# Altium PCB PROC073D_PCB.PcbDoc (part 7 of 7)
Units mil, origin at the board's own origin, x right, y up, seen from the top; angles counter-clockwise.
Board outline 2165.35 x 2695.12 mil, 8 copper layers (Top Layer, L2_GND, L3_SIGNAL 1, L4_SIGNAL 2, L5_SIGNAL 3, L6_SIGNAL 4, L7_GND, Bottom Layer), stack 56.1 mil thick; 414 components, 319 nets, 1353 pads, 1669 vias.
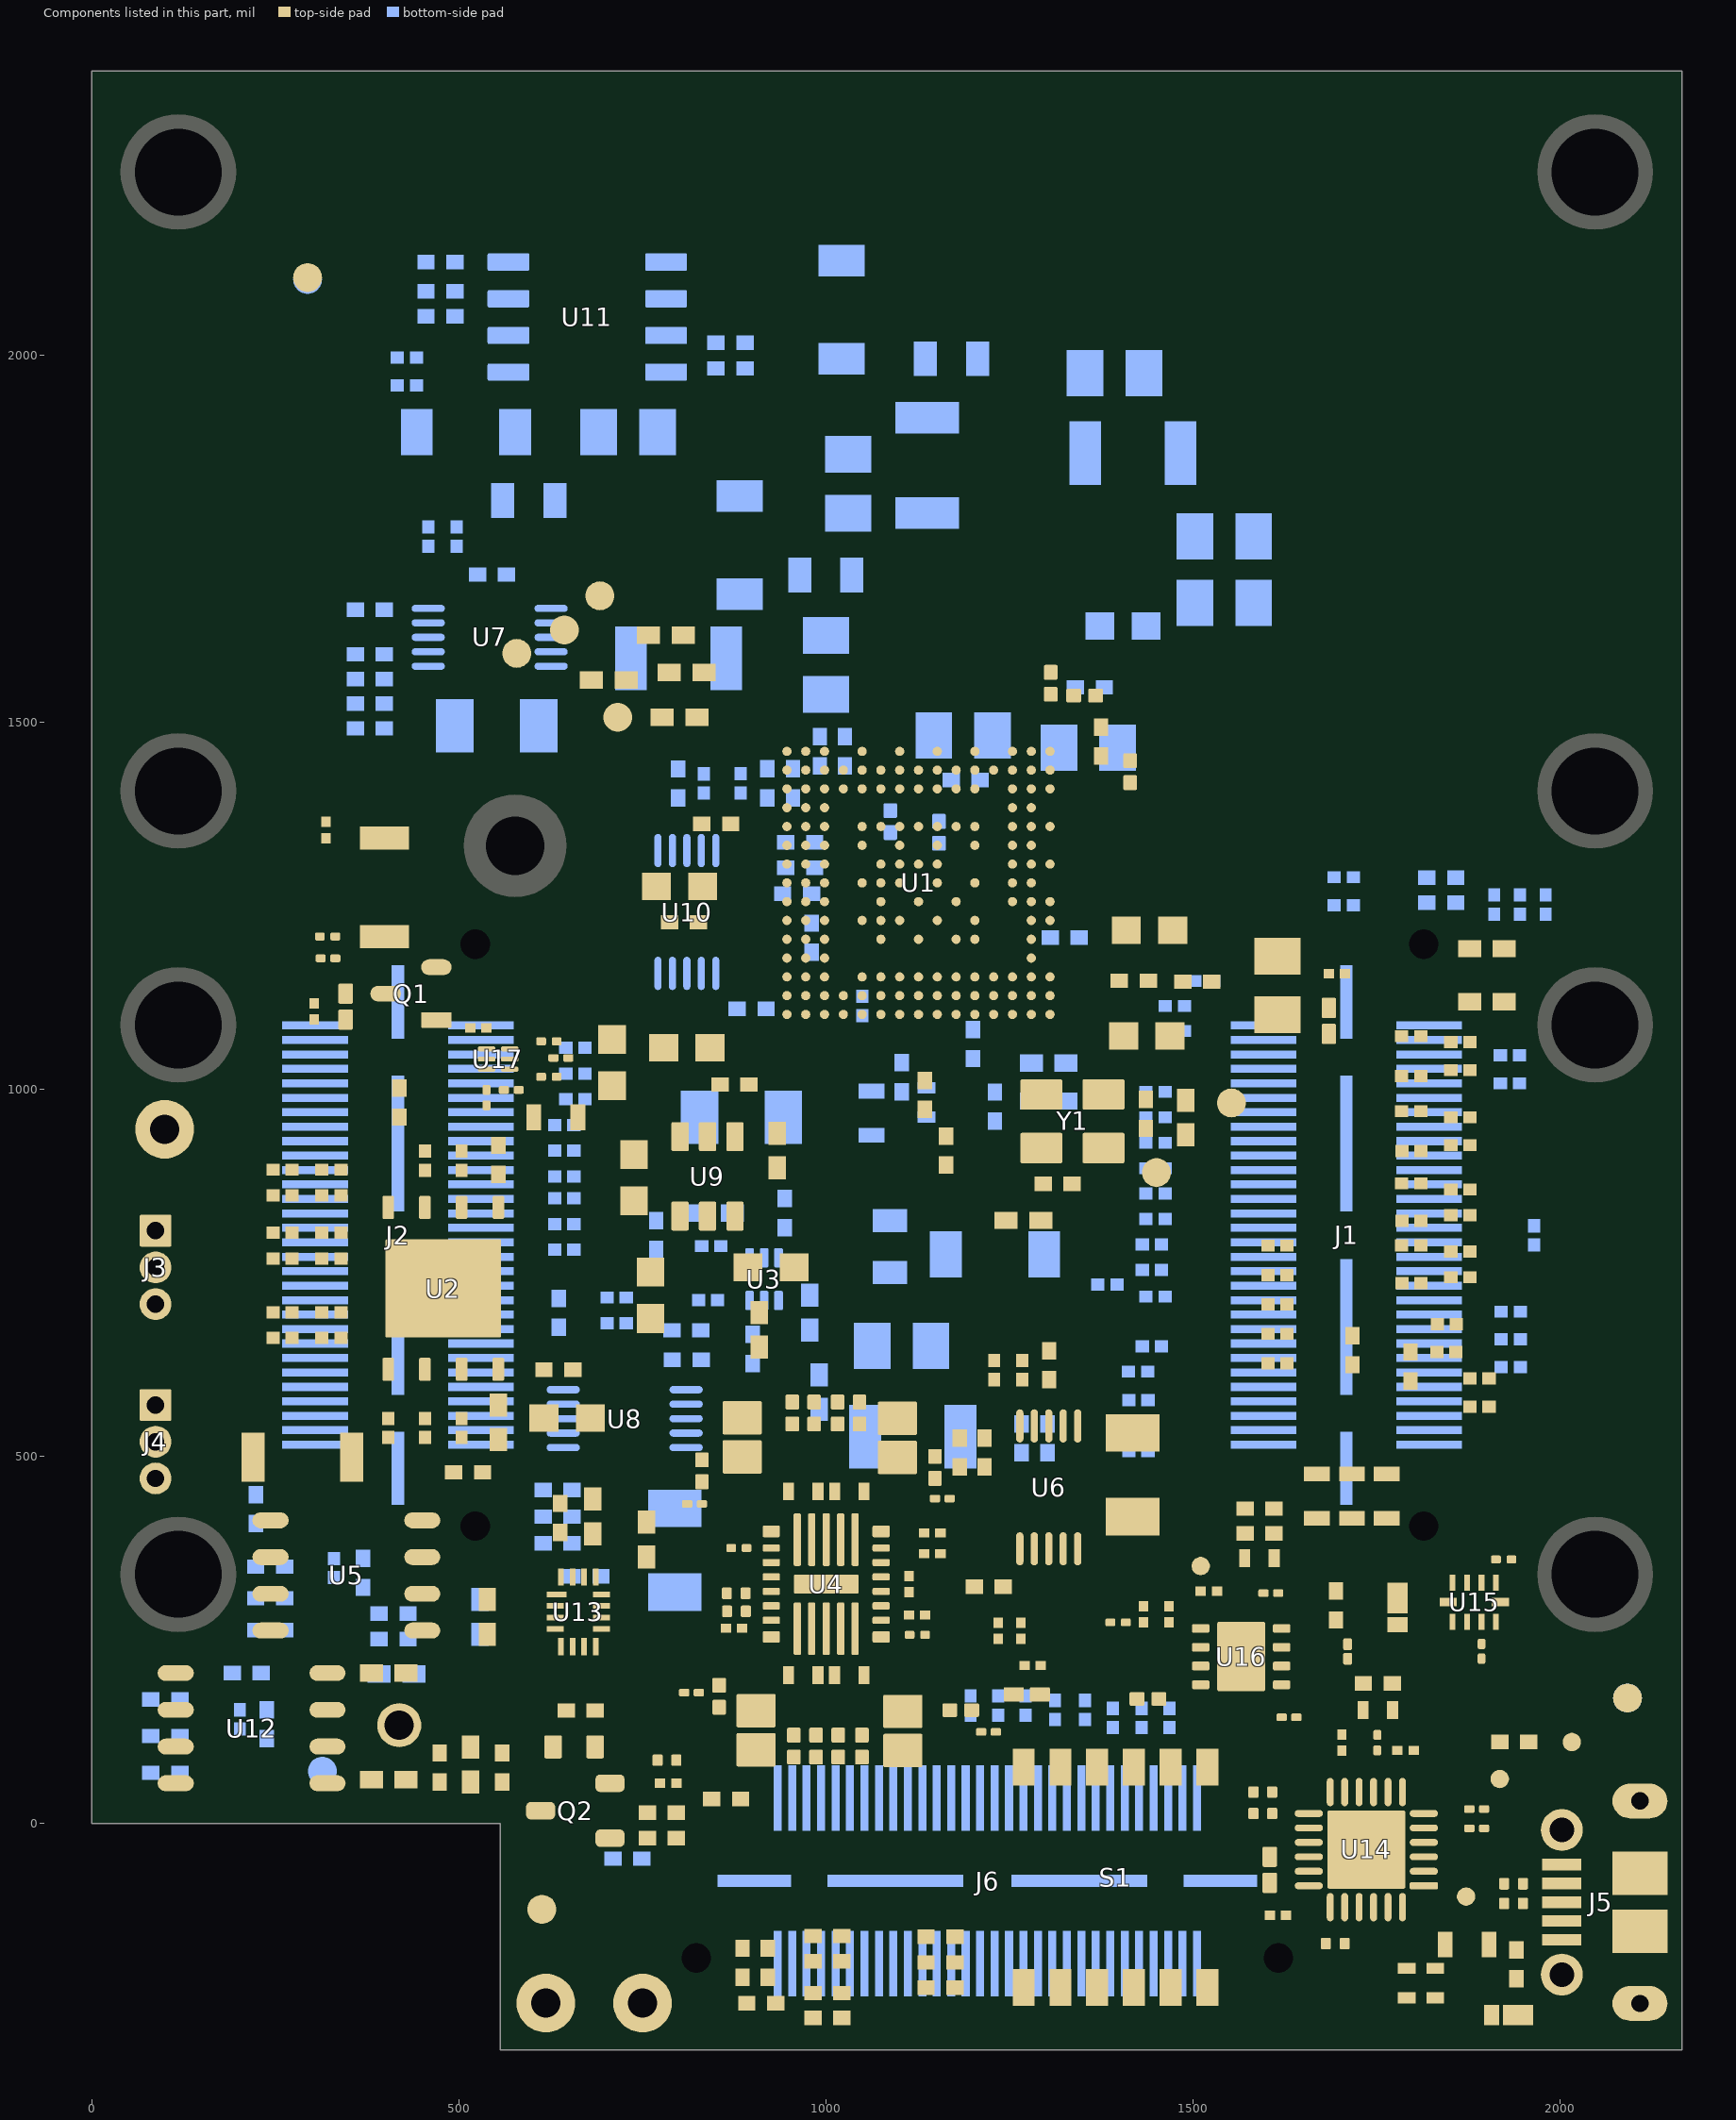
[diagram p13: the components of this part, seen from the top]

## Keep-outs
L2_GND:
  circle w1: c1074.8,1434.59 r7.87
  circle w1: c1177.16,1434.59 r7.87
  circle w1: c1125.98,1434.59 r7.87
  circle w1: c1279.53,1281.05 r7.87
  circle w1: c1279.52,1383.41 r7.87
  circle w1: c1279.52,1332.23 r7.87
  circle w1: c522.48,1197.95 r32
  circle w1: c1023.62,1434.59 r7.87
L3_SIGNAL 1:
  circle w1: c522.48,1197.95 r32
L5_SIGNAL 3:
  circle w1: c522.48,1197.95 r30
L7_GND:
  circle w1: c522.48,1196.95 r32
Bottom Layer:
  circle w1: c522.48,1197.95 r27.7
Keep-Out Layer:
  circle w1: c823.48,-182.98 r32
  circle w1: c1616,-182.98 r32
  circle w1: c522.48,1197.43 r32
  circle w1: c1813.86,1197.69 r32
  circle w1: c1813.86,405.17 r31
  circle w1: c522.48,404.91 r32
  lines w10: -5,-5 551.54,-5 551.54,-313.34 2170.35,-313.34 2170.35,2391.78 -5,2391.78 -5,-5
  text ".Layer_Name" at -423,-1637.06 h60

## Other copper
Top Layer:
  pour cut-out: 1039.36,1434.59 cw(c1023.62,1434.59) 1023.62,1418.85 cw(c1023.62,1434.59) 1007.88,1434.59 cw(c1023.62,1434.59) 1023.62,1450.33 cw(c1023.62,1434.59)
  pour cut-out: 1090.54,1434.59 cw(c1074.8,1434.59) 1074.8,1418.85 cw(c1074.8,1434.59) 1059.06,1434.59 cw(c1074.8,1434.59) 1074.8,1450.33 cw(c1074.8,1434.59)
  pour cut-out: 1141.72,1434.59 cw(c1125.98,1434.59) 1125.98,1418.85 cw(c1125.98,1434.59) 1110.24,1434.59 cw(c1125.98,1434.59) 1125.98,1450.33 cw(c1125.98,1434.59)
  pour cut-out: 1192.9,1434.59 cw(c1177.16,1434.59) 1177.16,1418.85 cw(c1177.16,1434.59) 1161.42,1434.59 cw(c1177.16,1434.59) 1177.16,1450.33 cw(c1177.16,1434.59)
  pour cut-out: 1295.26,1383.41 cw(c1279.52,1383.41) 1279.52,1367.67 cw(c1279.52,1383.41) 1263.78,1383.41 cw(c1279.52,1383.41) 1279.52,1399.15 cw(c1279.52,1383.41)
  pour cut-out: 1295.26,1332.23 cw(c1279.52,1332.23) 1279.52,1316.49 cw(c1279.52,1332.23) 1263.78,1332.23 cw(c1279.52,1332.23) 1279.52,1347.97 cw(c1279.52,1332.23)
  pour cut-out: 1295.26,1281.05 cw(c1279.52,1281.05) 1279.52,1265.31 cw(c1279.52,1281.05) 1263.78,1281.05 cw(c1279.52,1281.05) 1279.52,1296.79 cw(c1279.52,1281.05)
  pour cut-out: 556.52,-284.49 2140,-284.49 2140,2365.43 30,2365.43 29.99,0 0,0 0,2386.79 2165.35,2386.78 2165.36,-308.35 556.51,-308.34
  pour cut-out: 578.43,31.17 556.54,31.17 556.54,-284.48 578.43,-284.48
  pour cut-out: 578.43,31.17 29.99,31.17 29.99,0 578.43,0
  region net GND: 815.55,442.32 818.07,440.03 818.07,430.09 815.12,427.14 813.42,428.84 813.42,440.2
  region net GND: 816.41,441.54
  region net SW2_CAP: 824.15,446.21 824.15,427.99 826.75,425.39 828.9,427.54 828.9,443.25 825.66,446.48
  region net SW2_CAP: 823.19,446.32
  region net NetD1_2: 1921.76,-277.2 1926.51,-281.95 1926.51,-237.67 1921.76,-237.67
  region net 5V_IN_USB: 1913.29,-241.4 1916.65,-244.76 1916.65,-274.59 1913.28,-277.96 1909.04,-273.72 1909.04,-243.99 1910.77,-242.26
  region net 5V_IN_USB: 1913.62,-243.99
  region net NetD2_2: 1756.18,286.5 1795.39,286.5 1799.66,290.77 1757.72,290.77 1756.34,289.39
  region net 5V_IN: 1762.6,281.23 1802.62,281.23 1797.57,276.18 1762.22,276.18 1759.89,278.51
  region net GND: 1701.54,224.73 1701.54,228.44 1705.56,232.47 1723.33,232.47 1728.39,237.53 1728.39,230.46 1720.9,222.97 1703.31,222.97
  region net 5V_IN_SW: 1722.23,242.78 1717.81,242.78 1700.69,242.78 1695.5,237.59 1696.69,236.4 1715.85,236.4
  text ".Layer_Name" at -423,-1637.06 h60
L2_GND:
  pour cut-out: 1031.49,1434.59 cw(c1023.62,1434.59) 1023.62,1426.72 cw(c1023.62,1434.59) 1015.75,1434.59 cw(c1023.62,1434.59) 1023.62,1442.46 cw(c1023.62,1434.59)
  pour cut-out: 1031.49,1434.59 cw(c1023.62,1434.59) 1023.62,1426.72 cw(c1023.62,1434.59) 1015.75,1434.59 cw(c1023.62,1434.59) 1023.62,1442.46 cw(c1023.62,1434.59)
  pour cut-out: 1250,1044.43 1236,1030.43 1236,901.43 1257,880.43 1257,842.43 1263,836.43 1320,836.43 1344,860.43 1403,860.42 1411,868.43 1411,893.43 1433,915.43 1462,915.43 1470,923.43 1470,1000.43 1435,1035.43 1373,1035.43 1373,1054.43 1454.66,1054.43 1486.15,1022.93 1486.15,918.72 1465.09,897.66 1444.23,897.66 1426,879.43 1426,871.43 1397,842.43 1354.51,842.43 1329.44,817.37 1257.06,817.37 1236.03,838.4 1236.02,879.21 1216.02,899.23 1216.02,1040.43 1230.01,1054.42 1249.76,1054.43
  pour cut-out: 1236.78,1061.19 1245.87,1070.29 1245.87,1082.56 1075.37,1253.06 1075.37,1275.22 1033,1317.59 1033,1366.85 1014.95,1384.9 977.13,1422.72 977.13,1494.94 809.63,1662.44 809.63,2366.28 788,2366.28 788,1651.83 956.28,1483.55 956.28,1410.48 1012.83,1353.93 1012.83,1304.31 1057.82,1259.32 1057.82,1240.15
  pour cut-out: 2140.93,1585.87 1997.92,1585.87 1885.11,1473.06 1885.11,1444.65 1682.7,1242.24 1621.63,1242.24 1392.37,1242.24 1354.68,1204.55 1354.68,1127.22 1354.68,1040.8 1374.9,1040.8 1374.9,1151.62 1374.9,1194.05 1400.28,1219.43 1691.88,1219.43 1908.35,1435.9 1908.35,1460.99 2011.45,1564.09 2140.93,1564.09
  pour cut-out: 578.43,31.17 556.54,31.17 556.54,-284.48 578.43,-284.48
  pour cut-out: 556.52,-284.49 2140,-284.49 2140,2365.43 30,2365.43 29.99,0 0,0 0,2386.79 2165.35,2386.78 2165.36,-308.35 556.51,-308.34
  pour cut-out: 578.43,31.17 29.99,31.17 29.99,0 578.43,0
  pour cut-out: 1218.81,895.32 1218.81,879.53 1213.48,874.2 1221.37,866.31 1227.89,866.31 1227.89,871.64 1236.96,880.72 1224.73,892.95 1224.73,894.73
  pour cut-out: 1029,1382.43 1044,1382.43 1044,1367.19 1041.24,1364.43 1023,1364.43 1023,1376.43
  pour cut-out: 1060,1198.59 1075,1198.59 1075,1183.36 1072.23,1180.59 1054,1180.59 1054,1192.59
  pour cut-out: 1085.74,1196.59 1100.74,1196.59 1100.74,1181.36 1097.97,1178.59 1079.74,1178.59 1079.74,1190.59
  pour cut-out: 1255,1216.59 1270,1216.59 1270,1201.36 1267.23,1198.59 1249,1198.59 1249,1210.59
  pour cut-out: 1023.84,1257.18 1023.84,1272.18 1039.07,1272.18 1041.84,1269.41 1041.84,1251.18 1029.84,1251.18
  pour cut-out: 1031,1322.59 1046,1322.59 1046,1307.36 1043.23,1304.59 1025,1304.59 1025,1316.59
  pour cut-out: 885,1252.78 900,1252.78 900,1237.54 897.23,1234.78 879,1234.78 879,1246.78
  pour cut-out: 1158.84,1369.43 1158.84,1384.43 1174.07,1384.43 1176.84,1381.66 1176.84,1363.43 1164.84,1363.43
  pour cut-out: 1225.74,1184.36 1240.95,1190.79 1243.46,1180.6 1244.87,1176.68 1229.98,1169 1225.59,1183.89
  pour cut-out: 1223.69,1185.58 1242.47,1192.83 1246.63,1175.99 1229.52,1167.18 1223.69,1184.8
  text ".Layer_Name" at -423,-1637.06 h60
L3_SIGNAL 1:
  pour cut-out: 556.52,-284.49 2140,-284.49 2140,2365.43 30,2365.43 29.99,0 0,0 0,2386.79 2165.35,2386.78 2165.36,-308.35 556.51,-308.34
  pour cut-out: 578.43,31.17 29.99,31.17 29.99,0 578.43,0
  pour cut-out: 578.43,31.17 556.54,31.17 556.54,-284.48 578.43,-284.48
  pour cut-out: 1180.53,1386.9 1183,1384.43 1178.14,1379.57 1178.14,1366.29 1173.94,1362.1 1154.33,1362.1 1146.87,1369.56 1146.87,1375.5 1158.27,1386.9
  text ".Layer_Name" at -423,-1637.06 h60
L5_SIGNAL 3:
  pour cut-out: 578.43,31.17 556.54,31.17 556.54,-284.48 578.43,-284.48
  pour cut-out: 556.52,-284.49 2140,-284.49 2140,2365.43 30,2365.43 29.99,0 0,0 0,2386.79 2165.35,2386.78 2165.36,-308.35 556.51,-308.34
  pour cut-out: 578.43,31.17 29.99,31.17 29.99,0 578.43,0
  region net RADAR_QSPI_CS: 600.56,552.15
  pour cut-out: 1006.6,1594.42
  text ".Layer_Name" at -423,-1637.06 h60
L7_GND:
  pour cut-out: 578.43,31.17 556.54,31.17 556.54,-284.48 578.43,-284.48
  pour cut-out: 556.52,-284.49 2140,-284.49 2140,2365.43 30,2365.43 29.99,0 0,0 0,2386.79 2165.35,2386.78 2165.36,-308.35 556.51,-308.34
  pour cut-out: 578.43,31.17 29.99,31.17 29.99,0 578.43,0
  pour cut-out: 885.48,860.02 885.48,862.59 891.89,869 897.35,869 906.33,860.02 898.95,852.64 898.95,849.76 895.1,849.76 886.44,858.42
  pour cut-out: 1743.38,629.67 1743.38,632.24 1749.79,638.65 1755.25,638.65 1764.23,629.67 1756.85,622.29 1756.85,619.41 1753,619.41 1744.34,628.07
  pour cut-out: 1048,1202.49 1021.98,1202.49 1021.99,1220.02 1048,1220.02
  pour cut-out: 1048.65,1253.69 1022.63,1253.69 1022.64,1271.22 1048.65,1271.22
  pour cut-out: 1022.8,1324.95 1048.81,1324.95 1048.81,1307.41 1022.8,1307.41
  pour cut-out: 1180.98,1365.43 1154.96,1365.43 1154.96,1382.97 1180.98,1382.97
  pour cut-out: 1064,1200.43 1080,1184.43 1080,1180.43 1071,1171.43 1068,1171.43 1052,1187.43 1052,1194.43 1059,1201.43 1062,1201.43
  text ".Layer_Name" at -423,-1637.06 h60
L4_SIGNAL 2:
  pour cut-out: 578.43,31.17 556.54,31.17 556.54,-284.48 578.43,-284.48
  pour cut-out: 556.52,-284.49 2140,-284.49 2140,2365.43 30,2365.43 29.99,0 0,0 0,2386.79 2165.35,2386.78 2165.36,-308.35 556.51,-308.34
  pour cut-out: 578.43,31.17 29.99,31.17 29.99,0 578.43,0
  pour cut-out: 95.09,462.76 34.43,402.11 34.43,248.32 63.31,219.43 132.08,219.43 208.64,295.99 208.64,457.4 203.28,462.76
  pour cut-out: 606.77,-203.05 595.32,-203.05 574.72,-223.66 574.72,-271.99 598.01,-295.28 640.51,-295.28 664.11,-271.68 664.11,-228.06 640.51,-204.46
  text ".Layer_Name" at -423,-1637.06 h60
L6_SIGNAL 4:
  pour cut-out: 578.43,31.17 556.54,31.17 556.54,-284.48 578.43,-284.48
  pour cut-out: 556.52,-284.49 2140,-284.49 2140,2365.43 30,2365.43 29.99,0 0,0 0,2386.79 2165.35,2386.78 2165.36,-308.35 556.51,-308.34
  pour cut-out: 578.43,31.17 29.99,31.17 29.99,0 578.43,0
  text ".Layer_Name" at -423,-1637.06 h60
Bottom Layer:
  pour cut-out: 578.43,31.17 556.54,31.17 556.54,-284.48 578.43,-284.48
  pour cut-out: 556.52,-284.49 2140,-284.49 2140,2365.43 30,2365.43 29.99,0 0,0 0,2386.79 2165.35,2386.78 2165.36,-308.35 556.51,-308.34
  pour cut-out: 578.43,31.17 29.99,31.17 29.99,0 578.43,0
  pour cut-out: 263,2134.43 317,2188.43 880,2188.43 908,2160.43 908,2098.43 893,2083.43 274,2083.43 263,2094.43
  text ".Layer_Name" at -423,-1637.06 h60

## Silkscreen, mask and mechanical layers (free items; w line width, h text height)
Top Overlay:
  circle w6: c486.63,1402.09 r30
  circle w10: c1851.26,-90.22 r4.23
  rectangle: 1334.64,1437.44 1353.4,1473.8
  region: 1334.64,1489.71
  lines w6: 187.08,648.37 187.08,663.46 216.47,692.85 ; 203.5,897.76 198.92,893.18 198.92,786.66 214.76,770.82 ; 359.1,630.7 371.21,642.81 371.21,683.3 364.91,689.6 ; 479.38,497.57 497.97,497.57 500.7,500.3 ; 627.98,1907.74 627.98,1754.26 696.21,1754.26 ; 648.31,1016.63 654.42,1016.63 664.22,1026.43 664.22,1159.01 ; 657.67,-196.22 706.66,-147.23 ; 713.82,1771.85 713.82,1906.52 ; 726.18,1864.99 731.82,1859.36 731.82,1665.75 746.37,1651.2 ; 895.08,-55.65 923.22,-83.79 923.22,-145.7 ; 1024.91,-22.27 1033.92,-31.29 1033.92,-132.02 ; 1073.36,200.77 1098.69,200.77 1106.54,208.62 ; 1151.44,-53.19 1173.87,-75.62 1173.87,-132.25 ; 1164.06,461.56 1194.56,461.56 ; 1432.01,927.8 1432.01,910.65 1398.09,876.73 ; 1432.32,236.29 1432.32,257.47 ; 1460.96,324.94 1464.36,321.55 1464.36,313.48 ; 1486.06,380.76 1486.06,342.13 1491.66,336.53 ; 1552.22,441.76 1552.22,357.83 1555.67,354.37 ; 1622.2,14.4 1630.02,22.22 1630.02,38.52 ; 1636.74,-105.56 1651.26,-120.08 1651.26,-206.52 1647.26,-210.52 ; 1742.66,1043.42 1742.66,1048.18 1754.79,1060.31 ; 1750.24,-194.69 1765.99,-178.94 1810.5,-178.94 1813.92,-182.36 ; 1398.09,876.73 1408.09,876.73 1398.09,886.73 1398.09,876.73
  text "PROC073    REV D" at 498.37,1516.31 h45 r90
  text "C" at 1267.07,1500.27 h50
  text "C" at 473.15,1386 h50
  text ".Layer_Name" at -423,-1637.06 h60
Bottom Overlay:
  circle w6: c1519.56,1949.66 r30
  circle w6: c696.91,1476.87 r30
  circle w6: c667.74,1135.94 r30
  circle w6: c306.34,2022.03 r30
  lines w6: 190.46,462.35 196.84,455.97 196.84,388.99 210.64,375.18 ; 230.93,1048.86 249.25,1067.18 ; 260.27,1681.28 367.53,1681.28 367.53,1974.51 ; 603.52,363 603.52,211.13 609.81,204.84 ; 618.56,758.7 677.15,758.7 677.71,759.26 677.71,954.38 698.6,975.27 698.6,1081.8 638.79,1081.8 ; 722.34,1454.6 734.1,1442.84 775.46,1442.84 ; 779.7,1385.25 779.7,1456.44 931.48,1456.44 966.88,1491.84 975.56,1491.84 ; 849.15,668.59 869.41,648.34 869.41,604.48 ; 911.78,1303.56 925.28,1303.56 ; 915.72,796.02 915.72,863.46 ; 997.88,1408.3 1062.42,1408.3 1073.68,1419.57 1073.68,1469.29 1050.83,1492.14 1047.37,1492.14 ; 1457.62,2032.88 1457.62,2102.66 1701.27,2102.66 1701.27,2021.45 1701.27,1988.75 1590.42,1988.75 ; 1864.28,1231.5 1864.28,1223.35 1900.82,1186.81 ; 1872.86,515.65 1888.58,499.93 1888.54,457.99
  text "A" at 323.27,2006.33 h50
  text "B" at 1531.31,1932.8 h50
  text "B" at 708.67,1460 h50
  text "5V_IN" at 480.84,1240.74 h45
  text "A" at 684.67,1120.24 h50
  text "60" at 1938.04,1117.62 h60
  text "5V_IN" at 220.8,1086.19 h50 r270
  text "VPP_1P7" at 219.08,892.8 h40 r270
  text "1V8" at 1546.29,581.12 h40
  text "1V2" at 1546.95,549.97 h40
  text "3V3" at 1939.64,530.67 h40
  text "1V0" at 1544.85,512.29 h40
  text "2" at 589.41,507.23 h40
  text "1" at 228.35,497.9 h40
  text "5V_IN" at 1957.22,422.23 h40
  text "1" at 1549.43,389.07 h60
  text "TEXAS" at 1484.42,350.58 h70
  text "INSTRUMENTS" at 1583.13,294.25 h70
  text ".Layer_Name" at -423,-1637.06 h60
Top Paste:
  text ".Layer_Name" at -423,-1637.06 h60
Bottom Paste:
  text ".Layer_Name" at -423,-1637.06 h60
Top Solder:
  rectangle: 33,2226.43 1975.16,2365.43
  region: 1015.57,1478.49 1030.74,1478.49 1030.74,1450.49 1015.57,1450.49
  region: 1067.84,1478.49 1067.84,1450.49 1081.89,1450.49 1081.89,1478.49
  region: 1118.77,1478.49 1118.77,1450.49 1133.03,1450.49 1133.03,1478.49
  region: 1169.77,1478.49 1183.9,1478.49 1183.9,1450.49 1169.77,1450.49
  region: 1295.48,1391.49 1322.88,1391.49 1322.88,1376.49 1295.48,1376.49
  region: 1295.48,1339.49 1295.48,1325.49 1322.88,1325.49 1322.88,1339.49
  region: 1295.27,1288.52 1323.33,1288.52 1323.33,1274.56 1295.27,1274.52
  region: 1350.32,1556.89 1356.44,1550.76 1356.44,1519 1351.23,1513.78 1322.11,1513.78 1316.81,1508.47 1294.57,1486.24 1273.07,1486.24 1261.12,1474.29 1358.33,1474.29 1358.34,1501.48 1358.34,1510.01 1371.7,1523.38 1377.09,1523.38 1394.54,1540.83 1411.15,1540.83 1422.3,1551.75 1482.95,1551.75 1494.15,1540.55 1494.07,1443.96 1476.67,1426.56 1373.9,1426.56 1365.78,1418.44 1322.59,1418.44 1322.59,1248.74 1513.62,1248.81 1529.35,1233.08 1968.11,1233.08 1968.11,2237 760.21,2237 760.35,1726.22 802.77,1683.8 827.12,1659.45 867.94,1618.63 943,1543.57 943,1527.23 993.61,1476.63 1207.85,1476.63 1239.47,1508.25 1239.47,1521.82 1274.54,1556.89
  region: 183.52,1003.23 30,1003.23 30,2365.43 212.31,2365.43 212.31,1032.03
  region: 1952.32,289.61 1966.41,275.52 1966.41,248.99 1973.96,241.44 2140,241.6 2140,2365.43 1960,2365.43 1960,1036.43 2015,981.43 2015,466.43 1952.32,403.74
  text ".Layer_Name" at -423,-1637.06 h60
  text ".Layer_Name" at -423,-1637.06 h60
Bottom Solder:
  region: 1955.85,286.72 1967.77,274.79 1967.77,249.52 1975.39,241.91 2140,241.6 2140,2365.43 30,2365.43 30,1003.23 185.6,1003.23 205,1022.64 205,1334.43 241,1370.43 241,2112.72 335.84,2207.56 1940,2207.56 1940,1440.43 2020,1360.43 2020,1192.42 1962.25,1134.68 1962.25,1048.83 2015.39,995.69 2015.39,456.82 1955.85,397.27
  region: 1911.1,1447.33 1937.91,1446.96 2022.09,1362.78 2022.09,1356.45 2021.72,1356.08 1937.12,1356.08 1902.9,1390.3 1902.9,1439.13
  text ".Layer_Name" at -423,-1637.06 h60
Drill Guide:
  text ".Layer_Name" at -423,-1637.06 h60
M1 Board Outline:
  the board outline again, w10
  text ".Layer_Name" at -423,-1637.06 h60
M2 Board Dimensions:
  rectangle: -1000,-1053.57 -875,-928.57
  rectangle: -875,-1178.57 -500,-1053.57
  lines w7: -1000,-1053.57 0,-1053.57 ; -875,-1178.57 -875,-928.57 ; -750,-1178.57 -750,-928.57 ; -500,-1178.57 -500,-928.57 ; -250,-1178.57 -250,-928.57 ; -1000,-1178.57 0,-1178.57 0,-928.57 -1000,-928.57 -1000,-1178.57
  text ".Layer_Name" at -434.88,-1635.12 h60
M3 3D STEP Top:
  text ".Layer_Name" at -423,-1637.06 h60
M4 3D STEP Bottom:
  text ".Layer_Name" at -423,-1637.06 h60
M5 Assembly Top:
  lines w10: -1292,-1708.74 5308,-1708.74 ; -1292,-1505.4 5310,-1505.4 ; -1292,-1302.07 -1292,-1912.07 2713,-1912.07 5310,-1912.07 5310,-1302.07 -1291.5,-1302.07 -1291.5,-1912.07 284,-1912.07 ; 1173,-1912.07 1173,-1302.07 ; 2440,-1505.4 2440,-1302.07 ; 3280,-1505.4 3280,-1302.07 ; 3902,-1918.57 3902,-1715.74
  text "COMPONENTS MARKED 'DNP' SHOULD NOT BE POPULATED." at 153.5,-1097.07 h60
  text "ASSEMBLY VARIANT:" at 153,-1212.57 h60
  text ".VariantName" at 1189,-1212.57 h60
  text "PCB VIEWED FROM TOP SIDE" at -1228.5,-1434.24 h60
  text "BOARD #:" at 1248,-1434.24 h60
  text ".PRJ_Number" at 1793.5,-1434.24 h60
  text "REV:" at 2638,-1434.24 h60
  text ".PCB_Rev" at 2929.5,-1434.24 h60
  text "SVN REV:" at 3476,-1434.24 h60
  text ".VersionControl_RevNumber" at 3982,-1434.24 h60
  text "Assembly Layer Top" at -433,-1633.57 h60
  text "TID #:" at 1248,-1637.57 h60
  text ".TID" at 1793.5,-1637.57 h60
  text "PLOT NAME =" at -1228.5,-1842.91 h60
  text ".plot_File_Name" at -423,-1842.91 h60
  text "GENERATED    :" at 1250,-1842.91 h60
  text ".Print_Date" at 2119.5,-1842.91 h60
  text ".Print_Time" at 2848.5,-1842.91 h60
  text "TEXAS INSTRUMENTS" at 4113,-1842.91 h60
M6 Assembly Bottom:
  lines w6: 705,946.43 705,1086.43 ; 786.98,859.14 791.01,855.11 791.01,805.11 810.46,785.66 810.46,792.86 802.41,784.81 809.61,784.81 ; 833.84,1452.2 833.84,1469.69 ; 1770.26,1355.04 1770.26,1297.39 1798.64,1269 1798.64,1278.88 1788.68,1268.91 1796.09,1268.91 ; 705,1086.43 714.25,1077.18 695.75,1077.18 705,1086.43
  lines w10: -1292.5,-1505.9 5309.5,-1505.9 ; -1290.5,-1709.24 5309.5,-1709.24 ; 115.5,-1919.07 115.5,-1716.24 ; 737.5,-1505.9 737.5,-1302.57 ; 1577.5,-1505.9 1577.5,-1302.57 ; 2844.5,-1912.57 2844.5,-1302.57 ; 3733.5,-1912.57 5309,-1912.57 5309,-1302.57 -1292.5,-1302.57 -1292.5,-1912.57 1304.5,-1912.57 5309.5,-1912.57 5309.5,-1302.57
  text "59" at 350,1086.43 h45
  text "60" at 530.04,1086.86 h45
  text "59" at 1636,1086.86 h45
  text "60" at 1821.54,1086.86 h45
  text "1" at 325,496.43 h45
  text "2" at 525,496.43 h45
  text "1" at 1611,486.43 h45
  text "2" at 1822,486.43 h45
  text "COMPONENTS MARKED 'DNP' SHOULD NOT BE POPULATED." at 5102,-1096.57 h60
  text ".VariantName" at 4058,-1212.57 h60
  text "ASSEMBLY VARIANT:" at 5097,-1212.57 h60
  text ".VersionControl_RevNumber" at 35.5,-1434.74 h60
  text "SVN REV:" at 541.5,-1434.74 h60
  text ".PCB_Rev" at 1088,-1434.74 h60
  text "REV:" at 1379.5,-1434.74 h60
  text ".PRJ_Number" at 2224,-1434.74 h60
  text "BOARD #:" at 2769.5,-1434.74 h60
  text "PCB VIEWED FROM BOTTOM SIDE" at 5246,-1434.74 h60
  text "Assembly Bottom Layer" at 4885,-1623.57 h60
  text ".TID" at 2224,-1638.07 h60
  text "TID #:" at 2769.5,-1638.07 h60
  text "TEXAS INSTRUMENTS" at -95.5,-1843.41 h60
  text ".Print_Time" at 1169,-1843.41 h60
  text ".Print_Date" at 1898,-1843.41 h60
  text "GENERATED    :" at 2767.5,-1843.41 h60
  text ".plot_File_Name" at 4440.5,-1843.41 h60
  text "PLOT NAME =" at 5246,-1843.41 h60
M7 LPKF Text Top:
  lines w2: 1007.88,1434.59 1039.36,1434.59 ; 1015.75,1434.59 1031.49,1434.59 ; 1023.62,1418.85 1023.62,1450.33 ; 1023.62,1426.72 1023.62,1442.46
M9 Title Sheet:
  drawing of 57 lines, arcs and shapes, not listed
  text "1" at -260.16,7257.93 h70
  text "2" at 2235.5,7257.93 h70
  text "3" at 4724.84,7257.93 h70
  text "4" at 7231.51,7257.93 h70
  text "5" at 9730.5,7257.93 h70
  text "6" at 12235.5,7257.93 h70
  text "A" at -1416.5,6114.93 h70
  text "A" at 13383.5,6114.93 h70
  text "B" at -1416.5,3734.93 h70
  text "B" at 13383.5,3734.93 h70
  text "C" at -1416.5,1359.93 h70
  text "C" at 13383.5,1359.93 h70
  text "PROJECT TITLE:" at 10343.5,-501.07 h45
  text ".PRJ_Title" at 10393.5,-634.4 h70
  text "DESIGNED FOR:" at 10343.5,-802.07 h45
  text ".PRJ_Customer" at 10393.5,-942.07 h70
  text "D" at -1416.5,-1010.07 h70
  text "D" at 13383.5,-1010.07 h70
  text "FILE NAME:" at 10343.5,-1102.07 h45
  text ".PCB_File_Name_No_Path" at 10393.5,-1222.07 h70
  text "Texas Instruments (TI) and/or its licensors do not warrant the accuracy or completeness of this specification" at 5374,-1383.91 h45
  text "ENGINEER:" at 10343.5,-1392.07 h45
  text "LAYOUT BY:" at 11848.5,-1392.07 h45
  text "or any information contained therein. TI and/or its licensors do not warrant that this design will meet" at 5329.01,-1496.57 h45
  text ".PRJ_Engineer" at 10393.5,-1547.06 h70
  text ".PCB_Layout" at 11899,-1547.06 h70
  text "the specifications, will be suitable for your application or fit for any particular purpose, or will operate in" at 5329.01,-1609.24 h45
  text ".Layer_Name" at -413.7,-1644.05 h60
  text "ALTIUM DESIGNER VERSION:" at 11848.5,-1702.07 h45
  text "an implementation. TI and/or its licensors do not warrant that the design is production worthy. You should" at 5329.01,-1721.91 h45
  text "completely validate and test your design implementation to confirm the system functionality for your application." at 5374,-1834.57 h45
  text ".print_Scale" at 10393.5,-1835.4 h70
  text ".Application_BuildNumber" at 11899,-1835.4 h70
  text "1" at -260.16,-2042.07 h70
  text "2" at 2235.5,-2042.07 h70
  text "3" at 4724.84,-2042.07 h70
  text "4" at 7231.51,-2042.07 h70
  text "5" at 9730.5,-2042.07 h70
  text "WO # : 308145-8143-D" at 12235.5,-2042.07 h70
M10 Fab Notes:
  drawing of 198 lines, arcs and shapes, not listed
  text "DESIGN INFORMATION" at 11382.02,5577.6 h60
  text "MIN. TRACK WIDTH:" at 10737.46,5445.48 h60
  text "4" at 11833.7,5445.48 h60
  text "MIL" at 11988.46,5445.48 h60
  text "3.9" at 11781.69,5328.63 h60
  text "MIN. CLEARANCE:" at 10737.46,5321.35 h60
  text "MIL" at 11988.46,5321.35 h60
  text "MIN. VIA PAD SIZE:" at 10737.46,5197.23 h60
  text "13.77" at 11679,5192.43 h60
  text "MIL" at 12011,5188.43 h60
  text "EXTERNAL" at 12258.6,5069.92 h60
  text "0.0508mm (2.0MIL)" at 11432.46,5067.33 h60
  text "MINIMUM ANNULAR RING" at 10408.23,5059.1 h60
  text "PER" at 10608.23,4948.98 h60
  text "IPC-D-275 CLASS 2 LEVEL C" at 10828.23,4948.97 h60
  text "MIL, HOLES" at 12316.46,4848.5 h60
  text "+/-" at 11924,4839.91 h60
  text "+/-" at 12778,4839.91 h60
  text "REGISTRATION TOLERANCES:" at 10408.23,4838.85 h60
  text "METAL" at 11608,4838.85 h60
  text "5" at 12184.2,4838.85 h60
  text "3" at 13017.2,4838.85 h60
  text "MIL" at 13133.46,4838.85 h60
  text "HOLE SIZE TOLERANCE (UNLESS OTHERWISE SPECIFIED):" at 10408.23,4740.53 h60
  text "+/-" at 12778,4737.66 h60
  text "3" at 13017.2,4736.6 h60
  text "MIL" at 13133.46,4736.6 h60
  text "MATERIAL:" at 10333.46,4598.95 h60
  text "FR-4 High Tg" at 11319.9,4470.42 h60
  text "X" at 12062,4465.43 h60
  text "REFER STACK-UP" at 12562.85,4464.84 h55
  text "FR-408" at 10754.46,4457.92 h60
  text "OTHER" at 12242.46,4457.92 h60
  text "X" at 12233,4317.44 h60
  text "62 MIL (1.6mm) +/-10%" at 11074.56,4314.89 h60
  text "57.37 MIL +/-10%" at 12655,4308.43 h45
  text "THICKNESS:" at 10408.23,4306.67 h60
  text "OTHER" at 12359.46,4306.67 h60
  text "TOLERANCE:" at 10408.23,4168.35 h60
  text "X" at 11256.46,4168.35 h60
  text "ANSI IPC-6012 TYPE 3 CLASS 2" at 11434.48,4168.35 h60
  text "OTHER +/-" at 11434.46,4024.16 h60
  text "BOW & TWIST:" at 10408.23,3878.97 h60
  text "X" at 11256.46,3878.97 h60
  text "ANSI IPC-6012 TYPE 3 CLASS 2" at 11434.48,3878.97 h60
  text "OTHER +/-" at 11434.46,3732.28 h60
  text "DRILLING:" at 10333.46,3601.66 h60
  text "NC_DRILL FILES" at 12094.46,3496.47 h60
  text "REFERENCE:" at 10408.23,3492.53 h60
  text "X" at 11065.46,3492.44 h60
  text "AS SHOWN" at 11243.46,3492.53 h60
  text "X" at 11966.46,3492.53 h60
  text "OTHER" at 12392.46,3350.28 h60
  text "PTH COPPER THICKNESS:" at 10407.91,3346.75 h60
  text "X" at 11547.14,3346.75 h60
  text "20-30 um" at 11675.14,3346.75 h60
  text "BOARD FINISH:" at 10333.46,3199.15 h60
  text "SILKSCREEN:" at 10488.68,3089.03 h60
  text "X" at 11446.46,3089.03 h60
  text "TOP" at 11563.46,3089.03 h60
  text "X" at 11956.46,3089.03 h60
  text "BOTTOM" at 12074.46,3089.03 h60
  text "SILKSCREEN COLOR:" at 10488.68,2933.84 h60
  text "X" at 11445.46,2933.84 h60
  text "WHITE" at 11563.46,2933.84 h60
  text "OTHER" at 12074.46,2933.84 h60
  text "GREEN" at 11694.46,2790.39 h60
  text "X" at 12168.46,2790.39 h60
  text "OTHER" at 12312.46,2790.39 h60
  text "RED" at 12685,2790.39 h60
  text "SOLDER RESIST COLOR:" at 10488.68,2783.52 h60
  text "MATTE" at 11694.46,2636.14 h60
  text "SEMI-GLOSS" at 12312,2635.5 h60
  text "X" at 12168.06,2633.44 h60
  text "IMMERSION GOLD (ENIG)" at 11394.46,2463.37 h60
  text "ENEPIG" at 12732,2456.15 h60
  text "SURFACE FINISH:" at 10333.46,2455.15 h60
  text "IMM. TIN/SILVER OR EQUIV" at 10663,2317.83 h60
  text "X" at 10510,2315.15 h60
  text "OTHER" at 12094.46,2313.89 h60
  text "NOTES:" at 3534.49,2188.99 h60
  text "ARRAY/PANEL:" at 10333.46,2158.52 h60
  text "CUT AND TRIM PER M1 BOARD OUTLINE" at 11394.46,2150.29 h60
  text "N.C. ROUTE" at 11394.46,2014.33 h60
  text "X" at 12082.46,2014.33 h60
  text "V. SCORE" at 12260.46,2014.33 h60
  text "1. VIA'S ON PAD AND BGA PACKAGE AREA SHOULD BE FILLED WITH CONDUCTIVE MATERIAL AND SURFACE SHOULD BE FLAT" at 3563.63,2013.82 h60
  text "BGA AREA VIAS SHOULD BE CAPPED WITH COPPER PLATING TO ENSURE FLAT SURFACE" at 3670.36,1906.67 h60
  text "CERTIFICATION:" at 10333.46,1885.2 h60
  text "MATERIALS AND WORKMANSHIP FOR ALL PCBS" at 11058.46,1885.2 h60
  text "FLATNESS TOLERANCE FOR VIA ON PADS: +0.000 /- 0.001 INCHES ON BOTH SIDES." at 3670.36,1808.09 h60
  text "TO MEET OR EXCEED THE REQUIREMENTS OF:" at 11058.46,1791.14 h60
  text "OTHER THAN BGA AND VIA'S ON THE PAD  VIA FILLING REQUIREMENT CAN BE EXEMPTED" at 3670.36,1698.08 h60
  text "X" at 10695.97,1662.51 h60
  text "ANSI IPC-A-600F CLASS ->" at 10823.96,1662.51 h60
  text "X" at 12471.97,1662.51 h60
  text "2" at 12581.96,1662.51 h60
  text "1" at 12266.96,1661.01 h60
  text "3" at 12935.96,1661.01 h60
  text "2. VENDOR MAY ADJUST SOLDERMASK WHEREVER SOLDERMASK PADS ARE THE SAME SIZE (1:1) AS PER THE MANUFACTURING CAPABILITIES" at 3563.63,1570.41 h60
  text "X" at 11507.97,1514.82 h60
  text "RoHS" at 11635.96,1514.82 h60
  text "OTHER" at 12280.36,1514.82 h60
  text "PER ORDER" at 12677.42,1514.82 h60
  text "AND ALL OTHER SOLDER MASK PADS SHALL NOT BE MODIFIED, PROVIDED NO ADJACENT COPPER IS EXPOSED AND NO CONFLICT IS PRODUCED" at 3670.36,1471.41 h60
  text "WITH ANY STATED \"VIA TENTING/COVERING\" REQUIREMENTS." at 3670.36,1378.13 h60
  text "ALL BOARDS MUST MEET OR EXCEED UL94-V0 REQUIREMENTS." at 10361,1361 h60
  text "PCB MUST BEAR THE UL94V-0 UL REGISTERED MATERIAL ID NUMBER" at 10361,1244.93 h60
  text "3. MANUFACTURER'S IDENTIFICATION,DATECODE LETTER SHALL BE SILKSCREENED ON SOLDER SIDE OF THE BOARD." at 3563.63,1217.04 h60
  text "ADDITIONAL REQUIREMENTS:" at 10333.46,1075.51 h60
  text "4. TRACE WIDTH SHOULD BE ACCURATELY ETCHED. MAX TOLERANCE +/- 1 MIL." at 3563.63,1066.86 h60
  text "MICROSECTION:" at 10408.23,968.38 h60
  text "YES" at 11313.96,968.38 h60
  text "5. LAYER TO LAYER REGISTRATION SHALL BE WITHIN +/-2 MIL." at 3563.63,919.55 h60
  text "REQUIRED" at 12175.46,824.05 h60
  text "BARE BOARD ELEC. TEST:" at 10408.23,821.19 h60
  text "NONE" at 11713.96,821.19 h60
  text "X" at 12057.46,821.19 h60
  text "PER ORDER" at 12767.46,821.19 h60
  text "6. REFER IMPEDANCE TABLE FOR IMPEDANCE CONTROL TRACES ON LAYER 1, 3, 6 & 8." at 3563.63,775.09 h60
  text "XX MIL VIAS REQUIRE NON-CONDUCTIVE FILL AND PLANARIZE" at 10592,675.43 h59
  text "7. FOR ACCURACY OF THE ANTENNA DIMENSION, NEED TO BE MEASURE THE  ANTENNA DIMENSIONS ON ONE BAORD" at 3563.63,627.77 h60
  text "XX MIL VIAS REQUIRE CONDUCTIVE FILL AND PLANARIZE" at 10583,516.43 h60
  text "AS PER  ANTENNA DOCUMENT( Visio-IWR_60GHz4)." at 3670.36,507.35 h60
  text "OUTER XX MIL TRACES REQUIRE 50 OHM SINGLE-ENDED IMPEDANCE" at 10578.15,373.53 h58
  text "8. ALL VIAS ARE TENTED ON BOTH SIDES UNLESS OTHERWISE SOLDER MASK OPENED IN GERBER." at 3563.63,351.89 h60
  text "9. INTENTIONAL ONE NET ANTENNA VIA IS PRESENT IN DESIGN." at 3563.63,180.37 h60
  text "LAYER 1 & 6 (INNER LAYERS) XX MIL WIDE, XX MIL SPACE / TRACES REQUIRE 100 OHM DIFFERENTIAL IMPEDANCE" at 10617,123.43 h60
  text ".Layer_Name" at -425.59,-1637.69 h60
M11 Gerber Information:
  lines w10: -1292,-1708.74 5308,-1708.74 ; -1292,-1505.4 5310,-1505.4 ; -1292,-1302.07 -1292,-1912.07 2713,-1912.07 5310,-1912.07 5310,-1302.07 -1291.5,-1302.07 -1291.5,-1912.07 284,-1912.07 ; 1173,-1912.07 1173,-1302.07 ; 2440,-1505.4 2440,-1302.07 ; 3280,-1505.4 3280,-1302.07 ; 3902,-1918.57 3902,-1715.74
  text "ALL ARTWORK VIEWED FROM TOP SIDE" at -1228.5,-1434.24 h60
  text "BOARD #:" at 1248,-1434.24 h60
  text ".PRJ_Number" at 1793.5,-1434.24 h60
  text "REV:" at 2638,-1434.24 h60
  text ".PCB_Rev" at 2929.5,-1434.24 h60
  text "SVN REV:" at 3476,-1434.24 h60
  text ".VersionControl_RevNumber" at 3982,-1434.24 h60
  text "LAYER NAME =" at -1228.5,-1637.06 h60
  text "TID #:" at 1248,-1637.57 h60
  text ".TID" at 1793.5,-1637.57 h60
  text "PLOT NAME =" at -1228.5,-1842.91 h60
  text ".plot_File_Name" at -423,-1842.91 h60
  text "GENERATED    :" at 1250,-1842.91 h60
  text ".Print_Date" at 2119.5,-1842.91 h60
  text ".Print_Time" at 2848.5,-1842.91 h60
  text "TEXAS INSTRUMENTS" at 4113,-1842.91 h60
M12 Stackup:
  drawing of 562 lines, arcs and shapes, not listed
  text "LAYER STACK-UP :" at 5193.51,6770.46 h80
  text "Layer" at 5213.17,6600.19 h60
  text "Name" at 5623.08,6600.19 h60
  text "Material" at 6552.82,6600.19 h60
  text "Thickness" at 7412.59,6600.19 h60
  text "Constant" at 8062.42,6600.19 h60
  text "Board Layer Stack" at 8632.29,6600.19 h60
  text "1" at 5213.17,6480.19 h60
  text "Top Overlay" at 5623.08,6480.19 h60
  text "2" at 5213.17,6360.19 h60
  text "Top Solder" at 5623.08,6360.19 h60
  text "Solder Resist" at 6552.82,6360.19 h60
  text "0.80mil" at 7412.59,6360.19 h60
  text "1" at 8062.42,6360.19 h60
  text "6" at 5023.59,6241.31 h60
  text "3" at 5213.17,6240.19 h60
  text "Top Layer" at 5623.08,6240.19 h60
  text "Copper" at 6552.82,6240.19 h60
  text "1.60mil" at 7412.59,6240.19 h60
  text "4" at 5213.17,6120.19 h60
  text "Dielectric 1" at 5623.08,6120.19 h60
  text "RO4835 LOPRO" at 6552.82,6120.19 h60
  text "4.00mil" at 7412.59,6120.19 h60
  text "3.5" at 8062.42,6120.19 h60
  text "5" at 5213.17,6000.19 h60
  text "L2_GND" at 5623.08,6000.19 h60
  text "Copper" at 6552.82,6000.19 h60
  text "1.40mil" at 7412.59,6000.19 h60
  text "6" at 5213.17,5880.19 h60
  text "Dielectric 2" at 5623.08,5880.19 h60
  text "PCL370HR" at 6552.82,5880.19 h60
  text "5.50mil" at 7412.59,5880.19 h60
  text "4.17" at 8062.42,5880.19 h60
  text "6" at 5019.85,5763.04 h60
  text "7" at 5213.17,5760.19 h60
  text "L3_SIGNAL 1" at 5623.08,5760.19 h60
  text "Copper" at 6552.82,5760.19 h60
  text "1.40mil" at 7412.59,5760.19 h60
  text "8" at 5213.17,5640.19 h60
  text "Dielectric 3" at 5623.08,5640.19 h60
  text "PCL370HR" at 6552.82,5640.19 h60
  text "10.00mil" at 7412.59,5640.19 h60
  text "4.17" at 8062.42,5640.19 h60
  text "9" at 5213.17,5520.19 h60
  text "L4_SIGNAL 2" at 5623.08,5520.19 h60
  text "Copper" at 6552.82,5520.19 h60
  text "1.40mil" at 7412.59,5520.19 h60
  text "10" at 5213.17,5400.19 h60
  text "Dielectric 4" at 5623.08,5400.19 h60
  text "PCL370HR" at 6552.82,5400.19 h60
  text "5.50mil" at 7412.59,5400.19 h60
  text "4.17" at 8062.42,5400.19 h60
  text "11" at 5213.17,5280.19 h60
  text "L5_SIGNAL 3" at 5623.08,5280.19 h60
  text "Copper" at 6552.82,5280.19 h60
  text "1.40mil" at 7412.59,5280.19 h60
  text "12" at 5213.17,5160.19 h60
  text "Dielectric 5" at 5623.08,5160.19 h60
  text "PCL370HR" at 6552.82,5160.19 h60
  text "10.00mil" at 7412.59,5160.19 h60
  text "4.17" at 8062.42,5160.19 h60
  text "13" at 5213.17,5040.19 h60
  text "L6_SIGNAL 4" at 5623.08,5040.19 h60
  text "Copper" at 6552.82,5040.19 h60
  text "1.40mil" at 7412.59,5040.19 h60
  text "6" at 5022.17,5037.34 h60
  text "14" at 5213.17,4920.19 h60
  text "Dielectric 6" at 5623.08,4920.19 h60
  text "PCL370HR" at 6552.82,4920.19 h60
  text "5.50mil" at 7412.59,4920.19 h60
  text "4.17" at 8062.42,4920.19 h60
  text "15" at 5213.17,4800.19 h60
  text "L7_GND" at 5623.08,4800.19 h60
  text "Copper" at 6552.82,4800.19 h60
  text "1.40mil" at 7412.59,4800.19 h60
  text "16" at 5213.17,4680.19 h60
  text "Dielectric 7" at 5623.08,4680.19 h60
  text "PCL370HR" at 6552.82,4680.19 h60
  text "4.00mil" at 7412.59,4680.19 h60
  text "4.17" at 8062.42,4680.19 h60
  text "17" at 5213.17,4560.19 h60
  text "Bottom Layer" at 5623.08,4560.19 h60
  text "Copper" at 6552.82,4560.19 h60
  text "1.60mil" at 7412.59,4560.19 h60
  text "6" at 5025.35,4557.75 h60
  text "18" at 5213.17,4440.19 h60
  text "Bottom Solder" at 5623.08,4440.19 h60
  text "Solder Resist" at 6552.82,4440.19 h60
  text "0.80mil" at 7412.59,4440.19 h60
  text "1" at 8062.42,4440.19 h60
  text "19" at 5213.17,4320.19 h60
  text "Bottom Overlay" at 5623.08,4320.19 h60
  text "NOTE :" at 5225.04,4170.48 h60
  text "1. THIS IS AN IMPEDANCE CONTROLLED BOARD." at 5408.55,4065.46 h60
  text "2. EXTERNAL LAYER CU THICKNESSES ARE FINISHED THICKNESS AFTER PLATING." at 5408.55,3967.59 h60
  text "6" at 7261.89,3747.14 h60
  text "IMPEDANCE TABLE :" at 6105.5,3731.76 h80
  text "SPACING" at 6299.43,3576.01 h70
  text "LAYER" at 5549.43,3571.01 h70
  text "TRACE WIDTH" at 5814.43,3571.01 h70
  text "IMPEDANCE +/- 10%" at 6634.43,3571.01 h70
  text "REFERENCE LAYER" at 7359.43,3571.01 h70
  text "TOP" at 5584.43,3421.01 h70
  text "7.795 MILS" at 5869.43,3416.01 h65
  text "8 MILS" at 6324.43,3416.01 h65
  text "50 OHM" at 6744.43,3416.01 h65
  text "LAYER-2 (GND LAYER)" at 7309.43,3416.01 h65
  text "LAYER" at 5564.57,3201.93 h70
  text "TRACE WIDTH" at 5851.77,3201.09 h70
  text "SPACING" at 6336.77,3201.09 h70
  text "IMPEDANCE +/- 10%" at 6671.77,3201.09 h70
  text "REFERENCE LAYER" at 7396.77,3201.09 h70
  text "LAYER-2 AND" at 7510.74,3061.09 h65
  text "TOP AND" at 5529.48,3057.24 h70
  text "5.2 MILS" at 5952.73,3041.09 h65
  text "5 MILS" at 6385.52,3041.09 h65
  text "100 OHM" at 6853.75,3041.09 h65
  text "BOTTOM" at 5555.85,2988.55 h60
  text "LAYER-7" at 7581.18,2986.09 h65
  text "LAYER-2, LAYER 4 &" at 7412.84,2884.41 h65
  text "4.8 MILS" at 5951.98,2851.18 h65
  text "7.2 MIL" at 6380.02,2851.18 h65
  text "100 OHM" at 6853.75,2851.18 h65
  text "L3 & L6" at 5558.48,2849.72 h70
  text "LAYER-5, LAYER 7" at 7442.71,2814.02 h65
  text ".Layer_Name" at -423,-1637.06 h60
M13 Component Bodies Top:
  text ".Layer_Name" at -423,-1637.06 h60
M14 Component Bodies Bottom:
  text ".Layer_Name" at -423,-1637.06 h60
M15 Courtyards Top:
  text ".Layer_Name" at -423,-1637.06 h60
M16 Courtyards Bottom:
  text ".Layer_Name" at -423,-1637.06 h60
Drill Drawing:
  lines w8: -1243.55,3678.15 -1243.55,3796.86 -1116.65,3796.86 -1116.65,3678.15 -1243.55,3678.15 ; -1213.31,5928.53 -1086.41,5928.53 -1086.41,6047.24 -1213.31,6047.24 -1213.31,5928.53 ; -1213.31,6087.65 -1086.41,6087.65 -1086.41,6206.35 -1213.31,6206.35 -1213.31,6087.65 ; -1213.31,6261.38 -1086.41,6261.38 -1086.41,6380.08 -1213.31,6380.08 -1213.31,6261.38 ; -1213.31,6435.11 -1213.31,6553.81 -1086.41,6553.81 -1086.41,6435.11 -1213.31,6435.11
  lines w15: -1094.8,3658.52 4409.91,3658.52 ; -1094.8,3824.28 4409.91,3824.28 ; -1041.41,4761.67 4649.74,4761.67 ; -1041.41,6585.03 4649.74,6585.03 ; -644.32,3492.76 -644.32,3990.04 ; -590.92,4595.91 -590.92,6750.79 ; -165.78,3492.76 -165.78,3990.04 ; -112.38,4595.91 -112.38,6750.79 ; 682.97,3492.76 682.97,3990.04 ; 736.37,4595.91 736.37,6750.79 ; 1028.49,3492.76 1028.49,3990.04 ; 1081.89,4595.91 1081.89,6750.79 ; 1528.7,3492.76 1528.7,3990.04 ; 1582.1,4595.91 1582.1,6750.79 ; 2274.89,3492.76 2274.89,3990.04 ; 2331.28,4595.91 2331.28,6750.79 ; 3078,3492.76 3078,3990.04 ; 3134.39,4595.91 3134.39,6750.79 ; 3860.33,3492.76 3860.33,3990.04 ; 4100.16,4595.91 4100.16,6750.79 ; -1094.8,3492.76 4409.91,3492.76 4409.91,3990.04 -1094.8,3990.04 -1094.8,3492.76 ; -1041.41,4595.91 4649.74,4595.91 4649.74,6750.79 -1041.41,6750.79 -1041.41,4595.91
  text "Drill Table: Top Layer to Bottom Layer" at -916.05,6789.11 h80
  text "Symbol" at -941.95,6634.76 h96
  text "Hit Count" at -541.2,6634.76 h96
  text "Finished Hole Size" at -62.65,6634.76 h96
  text "Plated" at 786.1,6634.76 h96
  text "Hole Type" at 1131.62,6634.76 h96
  text "Physical Length" at 1631.83,6634.76 h96
  text "Rout Path Length" at 2381.01,6634.76 h96
  text "Drill Layer Pair" at 3184.11,6634.76 h96
  text "Tolerance" at 4149.89,6634.76 h96
  text "16" at -541.2,6469 h80
  text "7.87mil (0.200mm)" at -62.65,6469 h80
  text "PTH" at 786.1,6469 h80
  text "Round" at 1131.62,6469 h80
  text "-" at 1631.83,6469 h80
  text "-" at 2381.01,6469 h80
  text "Top Layer - Bottom Layer" at 3184.11,6469 h80
  text "+0/-7.874mil" at 4149.89,6469 h80
  text "8" at -1176.31,6454.02 h80
  text "B" at -976.81,6454.01 h73.67
  text "71" at -541.2,6303.24 h80
  text "8.00mil (0.203mm)" at -62.65,6303.24 h80
  text "PTH" at 786.1,6303.24 h80
  text "Round" at 1131.62,6303.24 h80
  text "-" at 1631.83,6303.24 h80
  text "-" at 2381.01,6303.24 h80
  text "Top Layer - Bottom Layer" at 3184.11,6303.24 h80
  text "+0/-8mil" at 4149.89,6303.24 h80
  text "C" at -976.81,6288.25 h73.67
  text "8" at -1176.31,6280.29 h80
  text "566" at -541.2,6137.48 h80
  text "12.20mil (0.310mm)" at -62.65,6137.48 h80
  text "PTH" at 786.1,6137.48 h80
  text "Round" at 1131.62,6137.48 h80
  text "-" at 1631.83,6137.48 h80
  text "-" at 2381.01,6137.48 h80
  text "Top Layer - Bottom Layer" at 3184.11,6137.48 h80
  text "+0/-12.2mil" at 4149.89,6137.48 h80
  text "D" at -976.81,6122.49 h73.67
  text "8" at -1176.31,6106.57 h80
  text "28" at -541.2,5971.72 h80
  text "15.00mil (0.381mm)" at -62.65,5971.72 h80
  text "PTH" at 786.1,5971.72 h80
  text "Round" at 1131.62,5971.72 h80
  text "-" at 1631.83,5971.72 h80
  text "-" at 2381.01,5971.72 h80
  text "Top Layer - Bottom Layer" at 3184.11,5971.72 h80
  text "+0/-15mil" at 4149.89,5971.72 h80
  text "E" at -976.81,5956.73 h73.67
  text "8" at -1176.31,5947.45 h80
  text "6" at -541.2,5805.96 h80
  text "23.62mil (0.600mm)" at -62.65,5805.96 h80
  text "PTH" at 786.1,5805.96 h80
  text "Round" at 1131.62,5805.96 h80
  text "-" at 1631.83,5805.96 h80
  text "-" at 2381.01,5805.96 h80
  text "Top Layer - Bottom Layer" at 3184.11,5805.96 h80
  text "+/-3mil" at 4149.89,5805.96 h80
  text "G" at -976.81,5790.97 h73.67
  text "2" at -541.2,5640.2 h80
  text "23.62mil (0.600mm)" at -62.65,5640.2 h80
  text "PTH" at 786.1,5640.2 h80
  text "Slot" at 1131.62,5640.2 h80
  text "51.18mil (1.300mm)" at 1631.83,5640.2 h80
  text "27.56mil (0.700mm)" at 2381.01,5640.2 h80
  text "Top Layer - Bottom Layer" at 3184.11,5640.2 h80
  text "+/-3mil" at 4149.89,5640.2 h80
  text "F" at -976.81,5625.21 h73.67
  text "2" at -541.2,5474.44 h80
  text "33.47mil (0.850mm)" at -62.65,5474.44 h80
  text "PTH" at 786.1,5474.44 h80
  text "Round" at 1131.62,5474.44 h80
  text "-" at 1631.83,5474.44 h80
  text "-" at 2381.01,5474.44 h80
  text "Top Layer - Bottom Layer" at 3184.11,5474.44 h80
  text "+/-3mil" at 4149.89,5474.44 h80
  text "H" at -976.81,5459.45 h73.67
  text "4" at -541.2,5308.68 h80
  text "40.00mil (1.016mm)" at -62.65,5308.68 h80
  text "PTH" at 786.1,5308.68 h80
  text "Round" at 1131.62,5308.68 h80
  text "-" at 1631.83,5308.68 h80
  text "-" at 2381.01,5308.68 h80
  text "Top Layer - Bottom Layer" at 3184.11,5308.68 h80
  text "+/-3mil" at 4149.89,5308.68 h80
  text "I" at -964.54,5293.69 h73.67
  text "6" at -541.2,5142.92 h80
  text "40.16mil (1.020mm)" at -62.65,5142.92 h80
  text "NPTH" at 786.1,5142.92 h80
  text "Round" at 1131.62,5142.92 h80
  text "-" at 1631.83,5142.92 h80
  text "-" at 2381.01,5142.92 h80
  text "Top Layer - Bottom Layer" at 3184.11,5142.92 h80
  text "+/-2mil" at 4149.89,5142.92 h80
  text "J" at -976.81,5127.93 h73.67
  text "1" at -541.2,4977.16 h80
  text "80.00mil (2.032mm)" at -62.65,4977.16 h80
  text "PTH" at 786.1,4977.16 h80
  text "Round" at 1131.62,4977.16 h80
  text "-" at 1631.83,4977.16 h80
  text "-" at 2381.01,4977.16 h80
  text "Top Layer - Bottom Layer" at 3184.11,4977.16 h80
  text "+/-3mil" at 4149.89,4977.16 h80
  text "K" at -976.81,4962.17 h73.67
  text "8" at -541.2,4811.4 h80
  text "118.11mil (3.000mm)" at -62.65,4811.4 h80
  text "PTH" at 786.1,4811.4 h80
  text "Round" at 1131.62,4811.4 h80
  text "-" at 1631.83,4811.4 h80
  text "-" at 2381.01,4811.4 h80
  text "Top Layer - Bottom Layer" at 3184.11,4811.4 h80
  text "+/-3mil" at 4149.89,4811.4 h80
  text "L" at -976.81,4796.41 h73.67
  text "710 Total" at -541.2,4645.64 h80
  text "Slot definitions :" at -941.95,4529.61 h80
  text "Rout Path Length" at -341,4529.61 h80
  text "= Calculated from tool start centre position to tool end centre position." at 295.11,4529.61 h80
  text "Physical Length" at -341,4463.3 h80
  text "= Rout Path Length + Tool Size = Slot length as defined in the PCB layout" at 247.67,4463.3 h80
  text "Drill Table: Layer 1 To Layer 2" at -1089.09,4022.94 h80
  text "Symbol" at -995.35,3874 h96
  text "Hit Count" at -594.59,3874 h96
  text "Finished Hole Size" at -116.05,3874 h96
  text "Plated" at 732.7,3874 h96
  text "Hole Type" at 1078.22,3874 h96
  text "Physical Length" at 1578.43,3874 h96
  text "Rout Path Length" at 2324.62,3874 h96
  text "Drill Layer Pair" at 3127.73,3874 h96
  text "Tolerance" at 3910.05,3874 h96
  text "988" at -594.59,3708.24 h80
  text "5.90mil (0.150mm)" at -116.05,3708.24 h80
  text "PTH" at 732.7,3708.24 h80
  text "Round" at 1078.22,3708.24 h80
  text "-" at 1578.43,3708.24 h80
  text "-" at 2324.62,3708.24 h80
  text "Top Layer - L2_GND" at 3127.73,3708.24 h80
  text "+0/-5.9mil" at 3910.05,3708.24 h80
  text "8" at -1206.55,3697.07 h80
  text "A" at -1030.21,3693.26 h73.67
  text "988 Total" at -594.59,3542.48 h80
  text ".Layer_Name" at -423,-1637.06 h60
M17 Embedded Cavity:
  text ".Layer_Name" at -423,-1637.06 h60
M18 Embedded Assembly:
  text ".Layer_Name" at -423,-1637.06 h60
M19 Embedded Keepout:
  text ".Layer_Name" at -423,-1637.06 h60

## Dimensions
11.06,-18.91 to 76.87,-71.44 on M2 Board Dimensions
556.54,-308.34 to 0,0 on M2 Board Dimensions
0,0 to 556.54,-308.34 on M2 Board Dimensions
0,2386.79 to 2165.35,2386.78 on M2 Board Dimensions
556.54,-308.34 to 0,2386.79 on M2 Board Dimensions
-1000,-1178.57 to 0,-1178.57 on M2 Board Dimensions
